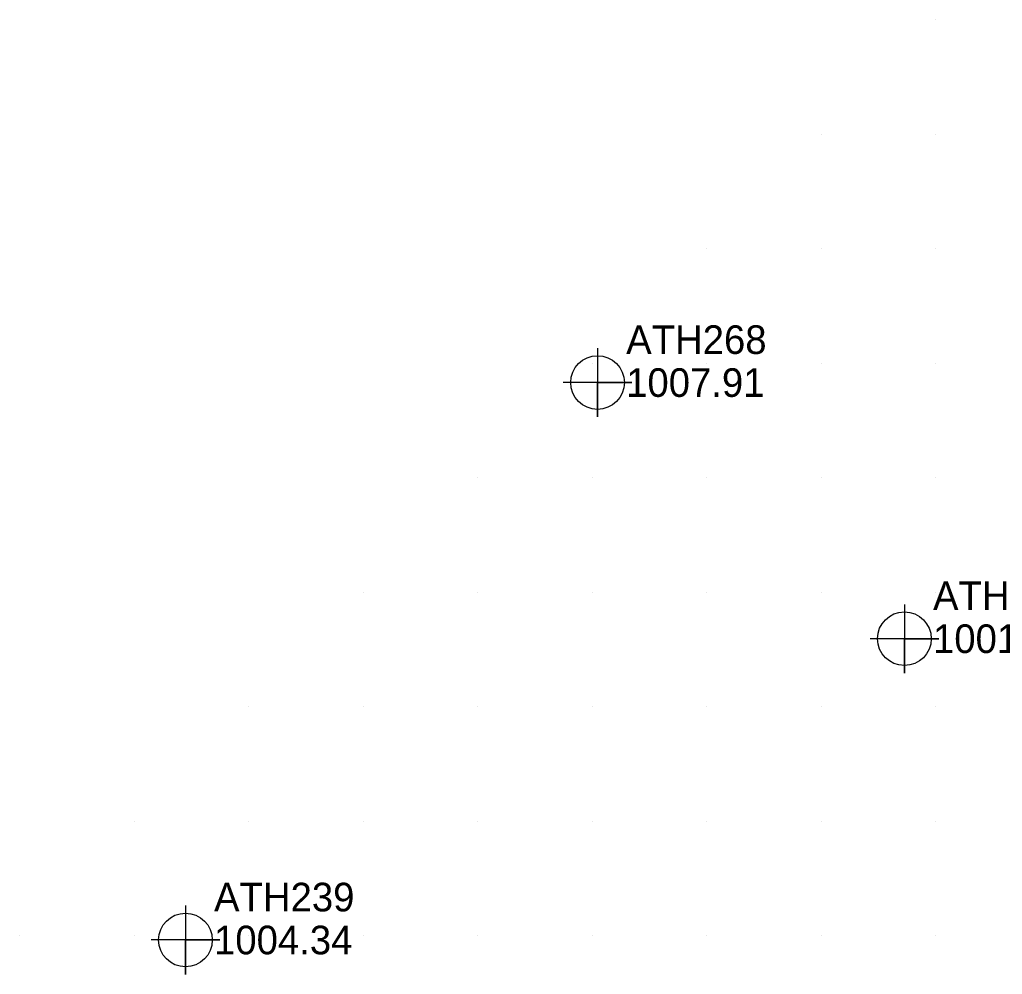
# Model space of a CAD drawing. Extents: x 1116680 to 1117499, y 661040 to 661703.
# Drawn here: x 1116770 to 1116855.8, y 661306.6 to 661390 of the extents above; entities that cross this region are included whole.
import ezdxf

# ---------------------------------------------------------------- set-up
doc = ezdxf.new("R2010")
doc.units = 0
for name, color, linetype in [('Exist DTM QL2 LIDAR Elevation Point', 7, 'Continuous'), ('Exist DTM Regular Point CELL', 7, 'Continuous'), ('Exist DTM Regular Point Cogo Elevation', 7, 'Continuous'), ('Exist DTM Regular Point Cogo Number', 7, 'Continuous')]:
    doc.layers.add(name, color=color, linetype=linetype)

msp = doc.modelspace()

# ---------------------------------------------------------------- linework, layer by layer
at = {"layer": 'Exist DTM QL2 LIDAR Elevation Point'}
for p, q in [((1116850, 661390), (1116850, 661390)), ((1116840, 661380), (1116840, 661380)), ((1116850, 661380), (1116850, 661380)), ((1116830, 661370), (1116830, 661370)), ((1116840, 661370), (1116840, 661370)), ((1116850, 661370), (1116850, 661370)), ((1116820, 661360), (1116820, 661360)), ((1116830, 661360), (1116830, 661360)), ((1116840, 661360), (1116840, 661360)), ((1116850, 661360), (1116850, 661360)), ((1116810, 661350), (1116810, 661350)), ((1116820, 661350), (1116820, 661350)), ((1116830, 661350), (1116830, 661350)), ((1116840, 661350), (1116840, 661350)), ((1116850, 661350), (1116850, 661350)), ((1116800, 661340), (1116800, 661340)), ((1116810, 661340), (1116810, 661340)), ((1116820, 661340), (1116820, 661340)), ((1116830, 661340), (1116830, 661340)), ((1116840, 661340), (1116840, 661340)), ((1116850, 661340), (1116850, 661340)), ((1116790, 661330), (1116790, 661330)), ((1116800, 661330), (1116800, 661330)), ((1116810, 661330), (1116810, 661330)), ((1116820, 661330), (1116820, 661330)), ((1116830, 661330), (1116830, 661330)), ((1116840, 661330), (1116840, 661330)), ((1116850, 661330), (1116850, 661330)), ((1116780, 661320), (1116780, 661320)), ((1116790, 661320), (1116790, 661320)), ((1116800, 661320), (1116800, 661320)), ((1116810, 661320), (1116810, 661320)), ((1116820, 661320), (1116820, 661320)), ((1116830, 661320), (1116830, 661320)), ((1116840, 661320), (1116840, 661320)), ((1116850, 661320), (1116850, 661320)), ((1116770, 661310), (1116770, 661310)), ((1116780, 661310), (1116780, 661310)), ((1116790, 661310), (1116790, 661310)), ((1116800, 661310), (1116800, 661310)), ((1116810, 661310), (1116810, 661310)), ((1116820, 661310), (1116820, 661310)), ((1116830, 661310), (1116830, 661310)), ((1116840, 661310), (1116840, 661310)), ((1116850, 661310), (1116850, 661310))]:
    msp.add_line(p, q, dxfattribs=at)
at = {"layer": 'Exist DTM Regular Point CELL'}
for points in [[(1116820.48, 661361.301), (1116820.48, 661355.301), (1116820.48, 661358.301), (1116823.48, 661358.301), (1116817.48, 661358.301)], [(1116847.283, 661338.93), (1116847.283, 661332.93), (1116847.283, 661335.93), (1116850.283, 661335.93), (1116844.283, 661335.93)], [(1116784.481, 661312.614), (1116784.481, 661306.614), (1116784.481, 661309.614), (1116787.481, 661309.614), (1116781.481, 661309.614)]]:
    msp.add_lwpolyline(points, dxfattribs=at)
for centre in [(1116820.48, 661358.301), (1116847.283, 661335.93), (1116784.481, 661309.614)]:
    msp.add_circle(centre, 2.344, dxfattribs=at)

# ---------------------------------------------------------------- texts
at = {"layer": 'Exist DTM Regular Point Cogo Elevation'}
for s, p in [('1007.91', (1116822.98, 661357.051)), ('1001.82', (1116849.783, 661334.68)), ('1004.34', (1116786.981, 661308.364))]:
    msp.add_text(s, height=2.5, dxfattribs=at).set_placement(p)
at = {"layer": 'Exist DTM Regular Point Cogo Number'}
for s, p in [('ATH268', (1116822.98, 661360.801)), ('ATH269', (1116849.783, 661338.43)), ('ATH239', (1116786.981, 661312.114))]:
    msp.add_text(s, height=2.5, dxfattribs=at).set_placement(p)

doc.saveas('drawing.dxf')
